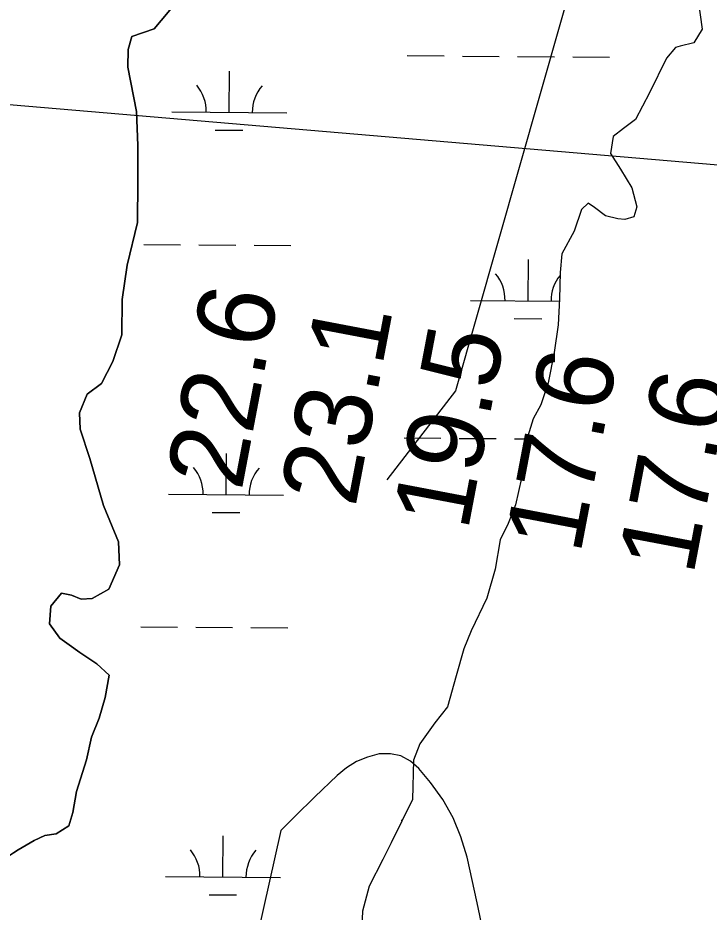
# Model space of a CAD drawing. Extents: x 3271442 to 3309282, y 752266 to 777610.
# Drawn here: x 3285019 to 3285621, y 762619 to 763397 of the extents above; entities that cross this region are included whole.
import ezdxf

# ---------------------------------------------------------------- set-up
doc = ezdxf.new("R2010")
doc.units = 0
for name, color, linetype in [('V-RIVR-RANG', 7, 'Continuous'), ('V-SITE-VEGE', 7, 'Continuous'), ('V-TOPO-DPTH', 7, 'Continuous'), ('V-TOPO-MINR', 7, 'Continuous'), ('V-TOPO-SHOR', 7, 'Continuous'), ('V-UTIL-LINE', 7, 'Continuous'), ('V-WETL-SWMP', 7, 'Continuous')]:
    doc.layers.add(name, color=color, linetype=linetype)

msp = doc.modelspace()

# ---------------------------------------------------------------- linework, layer by layer
at = {"layer": 'V-SITE-VEGE'}
for p, q in [((3285137.97, 763387.32), (3285157.55, 763410.75)), ((3285611.7, 763410.09), (3285614.9, 763386.93)), ((3285118.46, 763380.79), (3285137.97, 763387.32)), ((3285614.9, 763386.93), (3285607.5, 763375.2)), ((3285115.11, 763369.42), (3285118.46, 763380.79)), ((3285591.69, 763371.23), (3285583.93, 763361.71)), ((3285595.73, 763372.32), (3285591.69, 763371.23)), ((3285607.5, 763375.2), (3285595.73, 763372.32)), ((3285115.04, 763353.98), (3285115.11, 763369.42)), ((3285583.93, 763361.71), (3285569.1, 763331.65)), ((3285122.59, 763315.37), (3285115.04, 763353.98)), ((3285569.1, 763331.65), (3285556.86, 763308.55)), ((3285123.56, 763285.97), (3285122.59, 763315.37)), ((3285556.86, 763308.55), (3285546.54, 763300.52)), ((3285546.54, 763300.52), (3285537.32, 763293.57)), ((3285537.32, 763293.57), (3285535.06, 763278.89)), ((3285123.78, 763254.37), (3285123.56, 763285.97)), ((3285535.06, 763278.89), (3285543.81, 763265.25)), ((3285543.81, 763265.25), (3285553.66, 763249.04)), ((3285123.26, 763218.73), (3285123.78, 763254.37)), ((3285553.66, 763249.04), (3285558, 763232.48)), ((3285509.85, 763230.13), (3285503.52, 763211.42)), ((3285515.75, 763235.61), (3285509.85, 763230.13)), ((3285521.25, 763231.91), (3285515.75, 763235.61)), ((3285530.77, 763224.52), (3285521.25, 763231.91)), ((3285558, 763232.48), (3285555.39, 763223.68)), ((3285541.42, 763221.9), (3285530.77, 763224.52)), ((3285547.66, 763221.51), (3285541.42, 763221.9)), ((3285555.39, 763223.68), (3285547.66, 763221.51)), ((3285114.27, 763181.65), (3285123.26, 763218.73)), ((3285503.52, 763211.42), (3285492.78, 763191.62)), ((3285492.78, 763191.62), (3285491.24, 763175.46)), ((3285110.1, 763151.91), (3285114.27, 763181.65)), ((3285491.24, 763175.46), (3285490.77, 763152.31)), ((3285109.6, 763121.05), (3285110.1, 763151.91)), ((3285490.77, 763152.31), (3285489.56, 763129.91)), ((3285489.56, 763129.91), (3285486.15, 763105.67)), ((3285101.78, 763097.93), (3285109.6, 763121.05)), ((3285486.15, 763105.67), (3285480.89, 763079.23)), ((3285092.14, 763078.87), (3285101.78, 763097.93)), ((3285079.6, 763069.37), (3285092.14, 763078.87)), ((3285480.89, 763079.23), (3285474.56, 763060.15)), ((3285072.92, 763053.23), (3285079.6, 763069.37)), ((3285474.56, 763060.15), (3285467.89, 763048.06)), ((3285073.59, 763038.9), (3285072.92, 763053.23)), ((3285467.89, 763048.06), (3285463.04, 763033.01)), ((3285081.93, 763013.51), (3285073.59, 763038.9)), ((3285463.04, 763033.01), (3285461.51, 763019.43)), ((3285461.51, 763019.43), (3285457.74, 762996.29)), ((3285093.87, 762972.67), (3285081.93, 763013.51)), ((3285457.74, 762996.29), (3285452.49, 762973.17)), ((3285106.96, 762941.01), (3285093.87, 762972.67)), ((3285452.49, 762973.17), (3285446.17, 762957.03)), ((3285446.17, 762957.03), (3285439.12, 762942.73)), ((3285439.12, 762942.73), (3285434.6, 762917.03)), ((3285107.6, 762920.8), (3285106.96, 762941.01)), ((3285098.32, 762899.89), (3285107.6, 762920.8)), ((3285434.6, 762917.03), (3285427.51, 762892.07)), ((3285047.92, 762885.05), (3285057.15, 762896.4)), ((3285057.15, 762896.4), (3285065.96, 762894.53)), ((3285083.95, 762891.51), (3285098.32, 762899.89)), ((3285065.96, 762894.53), (3285074.4, 762891.18)), ((3285074.4, 762891.18), (3285083.95, 762891.51)), ((3285427.51, 762892.07), (3285413.79, 762863.47)), ((3285046.74, 762869.62), (3285047.92, 762885.05)), ((3285055.88, 762857.09), (3285046.74, 762869.62)), ((3285063.93, 762851.18), (3285055.88, 762857.09)), ((3285413.79, 762863.47), (3285407.47, 762847.7)), ((3285073.09, 762844.52), (3285063.93, 762851.18)), ((3285088.11, 762834.9), (3285073.09, 762844.52)), ((3285407.47, 762847.7), (3285400.75, 762824.22)), ((3285098.72, 762824.93), (3285088.11, 762834.9)), ((3285095.33, 762805.47), (3285098.72, 762824.93)), ((3285400.75, 762824.22), (3285393.28, 762797.43)), ((3285090.11, 762787.49), (3285095.33, 762805.47)), ((3285393.28, 762797.43), (3285382.2, 762783.51)), ((3285083.42, 762770.99), (3285090.11, 762787.49)), ((3285382.2, 762783.51), (3285369.25, 762765.2)), ((3285078.92, 762751.16), (3285083.42, 762770.99)), ((3285369.25, 762765.2), (3285363.68, 762750.89)), ((3285070.35, 762723.64), (3285078.92, 762751.16)), ((3285363.68, 762750.89), (3285362.79, 762716.72)), ((3285066.96, 762705.29), (3285070.35, 762723.64)), ((3285362.79, 762716.72), (3285344.25, 762678.96)), ((3285063.6, 762693.91), (3285066.96, 762705.29)), ((3285052.55, 762686.98), (3285063.6, 762693.91)), ((3285033.41, 762681.18), (3285042.62, 762685.55)), ((3285042.62, 762685.55), (3285052.55, 762686.98)), ((3285019.41, 762672.8), (3285033.41, 762681.18)), ((3285344.25, 762678.96), (3285336.84, 762664.66)), ((3284996.57, 762658.2), (3285019.41, 762672.8)), ((3285336.84, 762664.66), (3285324.98, 762641.2)), ((3285324.98, 762641.2), (3285319.37, 762619.54)), ((3285319.37, 762619.54), (3285318.58, 762606.31))]:
    msp.add_line(p, q, dxfattribs=at)
at = {"layer": 'V-TOPO-DPTH'}
msp.add_lwpolyline([(3285424.04, 762603.28), (3285419.01, 762626.89), (3285410.2, 762666.54), (3285404.96, 762684.11), (3285398.17, 762700.92), (3285389.07, 762716.6), (3285378.42, 762731.53), (3285368.33, 762743.72), (3285360.87, 762750.17), (3285352.72, 762754.73), (3285343.54, 762756.47), (3285333.68, 762756.33), (3285323.61, 762753.54), (3285314.08, 762749.68), (3285305.37, 762744.23), (3285297.2, 762737.7), (3285277.77, 762719.14), (3285260.52, 762702.28), (3285248.11, 762689.79), (3284865.15, 760978.94)], dxfattribs=at)
at = {"layer": 'V-TOPO-MINR'}
for points in [[(3285679.63, 763853.17), (3285639.75, 763792.02), (3285611.36, 763743.85), (3285586.01, 763694.3), (3285565.23, 763642.66), (3285547.49, 763589.64), (3285400.08, 763072.26), (3285340.44, 762994.78)], [(3285424.04, 762603.28), (3285419.01, 762626.89), (3285410.2, 762666.54), (3285404.96, 762684.11), (3285398.17, 762700.92), (3285389.07, 762716.6), (3285378.42, 762731.53), (3285368.33, 762743.72), (3285360.87, 762750.17), (3285352.72, 762754.73), (3285343.54, 762756.47), (3285333.68, 762756.33), (3285323.61, 762753.54), (3285314.08, 762749.68), (3285305.37, 762744.23), (3285297.2, 762737.7), (3285277.77, 762719.14), (3285260.52, 762702.28), (3285248.11, 762689.79)]]:
    msp.add_lwpolyline(points, dxfattribs=at)
at = {"layer": 'V-TOPO-SHOR'}
for points in [[(3285157.55, 763410.75), (3285137.97, 763387.32), (3285118.46, 763380.79), (3285115.11, 763369.42), (3285115.04, 763353.98), (3285122.59, 763315.37), (3285123.56, 763285.97), (3285123.78, 763254.37), (3285123.26, 763218.73), (3285114.27, 763181.65), (3285110.1, 763151.91), (3285109.6, 763121.05), (3285101.78, 763097.93), (3285092.14, 763078.87), (3285079.6, 763069.37), (3285072.92, 763053.23), (3285073.59, 763038.9), (3285081.93, 763013.51), (3285093.87, 762972.67), (3285106.96, 762941.01), (3285107.6, 762920.8), (3285098.32, 762899.89), (3285083.95, 762891.51), (3285074.4, 762891.18), (3285065.96, 762894.53), (3285057.15, 762896.4), (3285047.92, 762885.05), (3285046.74, 762869.62), (3285055.88, 762857.09), (3285063.93, 762851.18), (3285073.09, 762844.52), (3285088.11, 762834.9), (3285098.72, 762824.93), (3285095.33, 762805.47), (3285090.11, 762787.49), (3285083.42, 762770.99), (3285078.92, 762751.16), (3285070.35, 762723.64), (3285066.96, 762705.29), (3285063.6, 762693.91), (3285052.55, 762686.98), (3285042.62, 762685.55), (3285033.41, 762681.18), (3285019.41, 762672.8), (3284996.57, 762658.2)], [(3285611.7, 763410.09), (3285614.9, 763386.93), (3285607.5, 763375.2), (3285595.73, 763372.32), (3285591.68, 763371.23), (3285583.93, 763361.71), (3285569.1, 763331.65), (3285556.86, 763308.55), (3285546.54, 763300.52), (3285537.32, 763293.57), (3285535.06, 763278.89), (3285543.81, 763265.25), (3285553.66, 763249.04), (3285558, 763232.48), (3285555.39, 763223.68), (3285547.66, 763221.51), (3285541.42, 763221.9), (3285530.77, 763224.52), (3285521.25, 763231.91), (3285515.75, 763235.61), (3285509.85, 763230.13), (3285503.52, 763211.42), (3285492.78, 763191.62), (3285491.24, 763175.46), (3285490.77, 763152.31), (3285489.56, 763129.9), (3285486.15, 763105.67), (3285480.89, 763079.23), (3285474.56, 763060.16), (3285467.89, 763048.06), (3285463.04, 763033.01), (3285461.51, 763019.43), (3285457.74, 762996.29), (3285452.49, 762973.17), (3285446.17, 762957.03), (3285439.12, 762942.73), (3285434.6, 762917.03), (3285427.51, 762892.07), (3285413.79, 762863.47), (3285407.47, 762847.7), (3285400.75, 762824.22), (3285393.28, 762797.43), (3285382.2, 762783.51), (3285369.25, 762765.2), (3285363.68, 762750.89), (3285362.79, 762716.72), (3285344.25, 762678.96), (3285336.84, 762664.66), (3285324.98, 762641.2), (3285319.37, 762619.54), (3285318.58, 762606.32)]]:
    msp.add_lwpolyline(points, dxfattribs=at)
at = {"layer": 'V-UTIL-LINE'}
msp.add_lwpolyline([(3284680.99, 763349.58), (3290442.16, 762859.98), (3294363.62, 762975.03), (3296343.03, 765526.6)], dxfattribs=at)
at = {"layer": 'V-WETL-SWMP'}
for p, q in [((3285137.97, 763387.32), (3285157.55, 763410.75)), ((3285611.7, 763410.09), (3285614.9, 763386.93)), ((3285118.47, 763380.79), (3285137.97, 763387.32)), ((3285614.9, 763386.93), (3285607.5, 763375.2)), ((3285115.11, 763369.42), (3285118.47, 763380.79)), ((3285591.68, 763371.23), (3285583.93, 763361.71)), ((3285595.73, 763372.32), (3285591.68, 763371.23)), ((3285607.5, 763375.2), (3285595.73, 763372.32)), ((3285115.04, 763353.99), (3285115.11, 763369.42)), ((3285358.24, 763364.05), (3285390.24, 763363.78)), ((3285406.24, 763363.65), (3285438.24, 763363.39)), ((3285454.24, 763363.26), (3285486.24, 763362.99)), ((3285502.24, 763362.86), (3285534.23, 763362.6)), ((3285583.93, 763361.71), (3285569.09, 763331.65)), ((3285122.59, 763315.37), (3285115.04, 763353.99)), ((3285203.24, 763314.58), (3285203.53, 763350.58)), ((3285569.09, 763331.65), (3285556.87, 763308.55)), ((3285123.56, 763285.97), (3285122.59, 763315.37)), ((3285153.24, 763314.99), (3285253.23, 763314.17)), ((3285556.87, 763308.55), (3285546.54, 763300.51)), ((3285546.54, 763300.51), (3285537.32, 763293.57)), ((3285191.11, 763299.25), (3285215.11, 763299.05)), ((3285537.32, 763293.57), (3285535.05, 763278.89)), ((3285123.79, 763254.37), (3285123.56, 763285.97)), ((3285535.05, 763278.89), (3285543.81, 763265.25)), ((3285543.81, 763265.25), (3285553.66, 763249.04)), ((3285123.26, 763218.73), (3285123.79, 763254.37)), ((3285553.66, 763249.04), (3285558, 763232.49)), ((3285509.85, 763230.13), (3285503.52, 763211.42)), ((3285515.75, 763235.61), (3285509.85, 763230.13)), ((3285521.25, 763231.91), (3285515.75, 763235.61)), ((3285530.77, 763224.52), (3285521.25, 763231.91)), ((3285558, 763232.49), (3285555.39, 763223.68)), ((3285541.42, 763221.9), (3285530.77, 763224.52)), ((3285547.66, 763221.51), (3285541.42, 763221.9)), ((3285555.39, 763223.68), (3285547.66, 763221.51)), ((3285114.28, 763181.66), (3285123.26, 763218.73)), ((3285503.52, 763211.42), (3285492.78, 763191.62)), ((3285128.88, 763199.76), (3285160.88, 763199.49)), ((3285176.88, 763199.36), (3285208.88, 763199.1)), ((3285224.88, 763198.97), (3285256.87, 763198.7)), ((3285492.78, 763191.62), (3285491.24, 763175.46)), ((3285463.33, 763150.57), (3285463.63, 763186.57)), ((3285110.1, 763151.91), (3285114.28, 763181.66)), ((3285491.24, 763175.46), (3285490.77, 763152.31)), ((3285109.6, 763121.05), (3285110.1, 763151.91)), ((3285490.77, 763152.31), (3285489.56, 763129.9)), ((3285413.33, 763150.98), (3285490.66, 763150.35)), ((3285451.2, 763135.24), (3285475.2, 763135.04)), ((3285489.56, 763129.9), (3285486.15, 763105.67)), ((3285101.78, 763097.93), (3285109.6, 763121.05)), ((3285486.15, 763105.67), (3285480.89, 763079.24)), ((3285092.14, 763078.87), (3285101.78, 763097.93)), ((3285079.6, 763069.37), (3285092.14, 763078.87)), ((3285480.89, 763079.24), (3285474.56, 763060.16)), ((3285072.92, 763053.23), (3285079.6, 763069.37)), ((3285474.56, 763060.16), (3285467.89, 763048.06)), ((3285073.59, 763038.9), (3285072.92, 763053.23)), ((3285467.89, 763048.06), (3285463.04, 763033.02)), ((3285081.93, 763013.51), (3285073.59, 763038.9)), ((3285355.5, 763031.38), (3285387.5, 763031.12)), ((3285403.5, 763030.99), (3285435.5, 763030.73)), ((3285451.5, 763030.59), (3285462.76, 763030.5)), ((3285463.04, 763033.02), (3285461.51, 763019.43)), ((3285461.51, 763019.43), (3285457.74, 762996.3)), ((3285093.87, 762972.67), (3285081.93, 763013.51)), ((3285200.5, 762981.92), (3285200.79, 763017.92)), ((3285457.74, 762996.3), (3285452.49, 762973.17)), ((3285150.5, 762982.33), (3285250.49, 762981.51)), ((3285106.96, 762941.01), (3285093.87, 762972.67)), ((3285452.49, 762973.17), (3285446.17, 762957.03)), ((3285188.37, 762966.59), (3285212.37, 762966.39)), ((3285446.17, 762957.03), (3285439.13, 762942.73)), ((3285439.13, 762942.73), (3285434.6, 762917.03)), ((3285107.6, 762920.8), (3285106.96, 762941.01)), ((3285098.32, 762899.9), (3285107.6, 762920.8)), ((3285434.6, 762917.03), (3285427.51, 762892.07)), ((3285047.92, 762885.05), (3285057.16, 762896.4)), ((3285057.16, 762896.4), (3285065.97, 762894.53)), ((3285083.96, 762891.51), (3285098.32, 762899.9)), ((3285065.97, 762894.53), (3285074.4, 762891.18)), ((3285074.4, 762891.18), (3285083.96, 762891.51)), ((3285427.51, 762892.07), (3285413.79, 762863.47)), ((3285046.75, 762869.63), (3285047.92, 762885.05)), ((3285055.88, 762857.09), (3285046.75, 762869.63)), ((3285126.14, 762867.09), (3285158.14, 762866.83)), ((3285174.14, 762866.7), (3285206.14, 762866.44)), ((3285222.14, 762866.3), (3285254.13, 762866.04)), ((3285063.94, 762851.18), (3285055.88, 762857.09)), ((3285413.79, 762863.47), (3285407.47, 762847.7)), ((3285073.09, 762844.52), (3285063.94, 762851.18)), ((3285088.11, 762834.9), (3285073.09, 762844.52)), ((3285407.47, 762847.7), (3285400.75, 762824.22)), ((3285098.73, 762824.93), (3285088.11, 762834.9)), ((3285095.33, 762805.47), (3285098.73, 762824.93)), ((3285400.75, 762824.22), (3285393.28, 762797.43)), ((3285090.11, 762787.49), (3285095.33, 762805.47)), ((3285393.28, 762797.43), (3285382.2, 762783.51)), ((3285083.42, 762770.99), (3285090.11, 762787.49)), ((3285382.2, 762783.51), (3285369.26, 762765.2)), ((3285078.92, 762751.17), (3285083.42, 762770.99)), ((3285369.26, 762765.2), (3285363.68, 762750.89)), ((3285070.35, 762723.64), (3285078.92, 762751.17)), ((3285363.68, 762750.89), (3285362.79, 762716.72)), ((3285066.96, 762705.29), (3285070.35, 762723.64)), ((3285362.79, 762716.72), (3285344.25, 762678.96)), ((3285063.6, 762693.91), (3285066.96, 762705.29)), ((3285052.55, 762686.98), (3285063.6, 762693.91)), ((3285352.76, 762698.72), (3285353.95, 762698.71)), ((3285033.42, 762681.18), (3285042.62, 762685.55)), ((3285042.62, 762685.55), (3285052.55, 762686.98)), ((3285197.76, 762649.25), (3285198.05, 762685.25)), ((3285019.42, 762672.8), (3285033.42, 762681.18)), ((3285344.25, 762678.96), (3285336.84, 762664.66)), ((3284996.57, 762658.2), (3285019.42, 762672.8)), ((3285336.84, 762664.66), (3285324.98, 762641.2)), ((3285147.76, 762649.67), (3285247.75, 762648.84)), ((3285324.98, 762641.2), (3285319.37, 762619.54)), ((3285185.63, 762633.92), (3285209.63, 762633.72)), ((3285319.37, 762619.54), (3285318.58, 762606.32))]:
    msp.add_line(p, q, dxfattribs=at)
for centre, start, end in [((3285148, 763315.51), 358.75626, 40.29991), ((3285258.48, 763314.6), 138.75625, 180.29991), ((3285408.09, 763151.5), 358.75626, 40.29991), ((3285518.57, 763150.59), 141.00503, 180.29991), ((3285145.26, 762982.85), 358.75626, 40.29991), ((3285255.74, 762981.94), 138.75625, 180.29991), ((3285142.52, 762650.18), 358.75626, 40.29991), ((3285253, 762649.27), 138.75625, 180.29991)]:
    msp.add_arc(centre, 35.25, start, end, dxfattribs=at)

# ---------------------------------------------------------------- texts
at = {"layer": 'V-RIVR-RANG'}
for s, p in [('22.6', (3285213.87, 762984.49)), ('23.1', (3285312.94, 762970.18)), ('19.5', (3285410.78, 762949.39)), ('17.6', (3285508.72, 762929.12)), ('17.6', (3285607, 762910.66))]:
    msp.add_text(s, height=67, rotation=79.21833, dxfattribs=at).set_placement(p)

doc.saveas('drawing.dxf')
